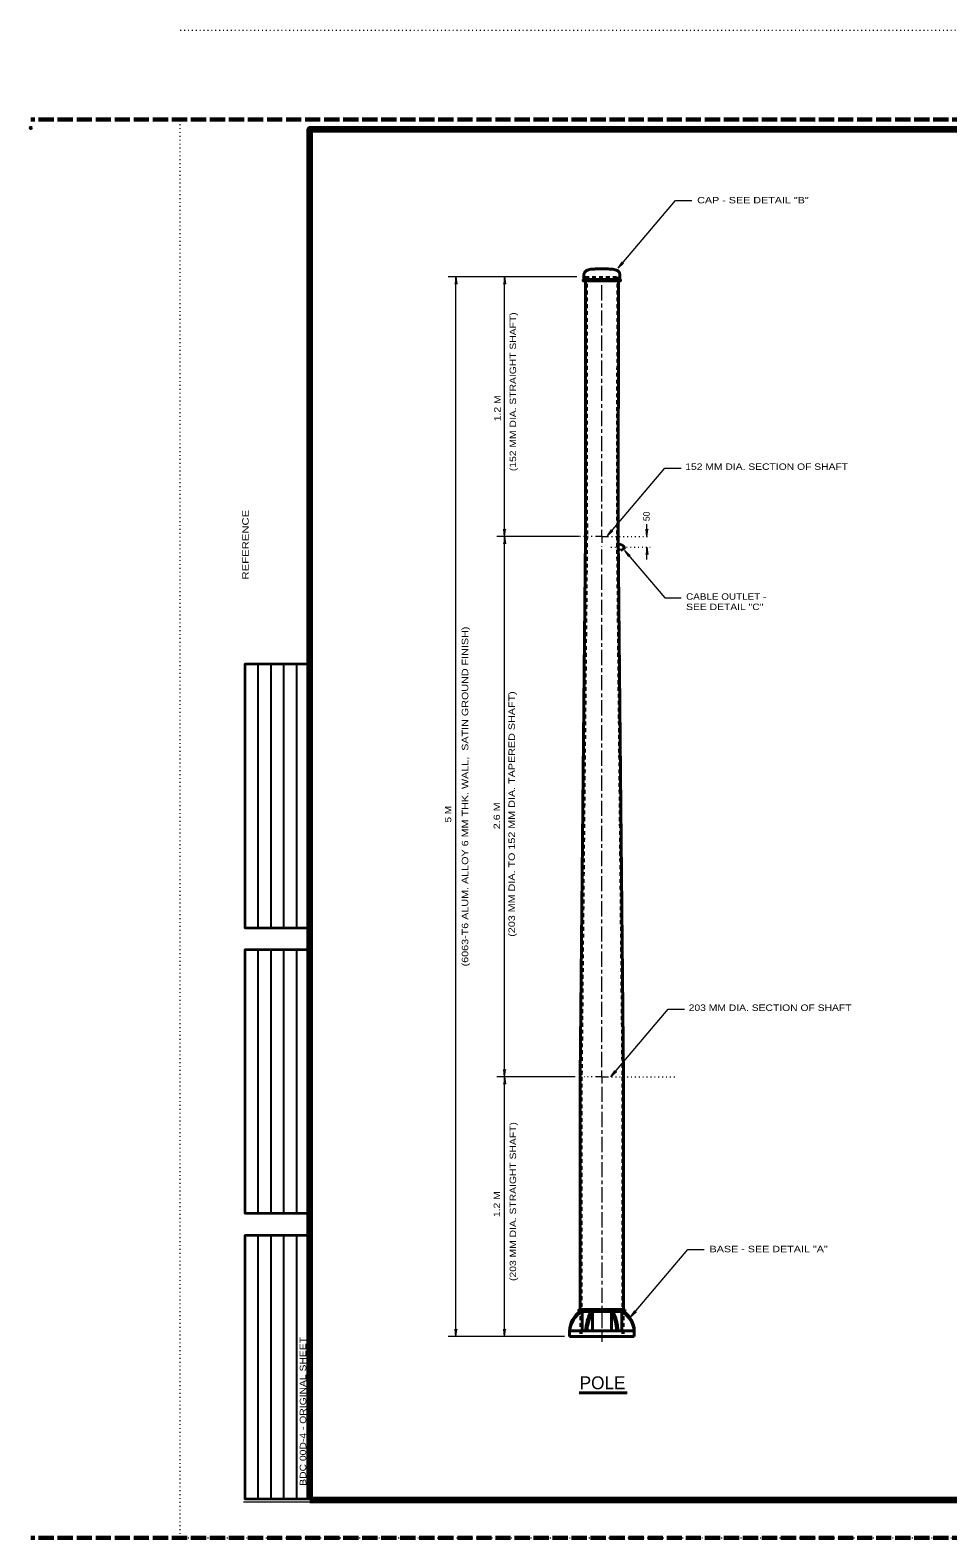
# Model space of a CAD drawing. Extents: x 312583 to 312854, y 144419 to 144597.
# Drawn here: x 312583.5 to 312691.9, y 144418.6 to 144596.8 of the extents above; entities that cross this region are included whole.
import ezdxf
from ezdxf.enums import TextEntityAlignment as Align

# ---------------------------------------------------------------- set-up
doc = ezdxf.new("R2010")
doc.units = 0
doc.header["$LTSCALE"] = 0.3
doc.header["$PDMODE"] = 32
doc.header["$PDSIZE"] = 0.15
for name, pattern in [('DOTTED', [1.5, 0.3, -1.2]), ('LONG_DASH_SHORT_DASH', [9.9, 6, -1.2, 1.5, -1.2]), ('LONG_DASHED', [7.5, 6, -1.5]), ('SHORT_DASHED', [2.7, 1.5, -1.2])]:
    doc.linetypes.add(name, pattern=pattern)
for name, color, linetype, lineweight in [('1', 7, 'Continuous', 40), ('2', 7, 'Continuous', 13), ('62', 7, 'DOTTED', 13), ('63', 7, 'LONG_DASHED', 60)]:
    doc.layers.add(name, color=color, linetype=linetype, lineweight=lineweight)

msp = doc.modelspace()

# ---------------------------------------------------------------- linework, layer by layer
at = {"layer": '1'}
for p, q in [((312653.15, 144567.2982), (312648.8413, 144567.2982)), ((312648.918, 144567.2982), (312648.918, 144567.7812)), ((312649.079, 144567.1372), (312651.034, 144567.1372)), ((312652.9967, 144567.1372), (312651.034, 144567.1372)), ((312653.15, 144567.2982), (312653.15, 144567.7812)), ((312653.15, 144567.2982), (312653.2343, 144567.2982)), ((312648.481, 144473.0595), (312648.481, 144445.5898)), ((312653.5947, 144473.0595), (312653.5947, 144445.5898)), ((312648.32, 144445.5898), (312651.034, 144445.5898)), ((312648.32, 144445.5898), (312648.32, 144445.3522)), ((312653.7557, 144445.5898), (312651.034, 144445.5898)), ((312653.7557, 144445.5898), (312653.7557, 144445.3522)), ((312648.32, 144445.3522), (312651.034, 144445.3522)), ((312648.688, 144443.0368), (312648.688, 144445.3522)), ((312649.9223, 144445.3522), (312649.9223, 144443.1135)), ((312653.7557, 144445.3522), (312651.034, 144445.3522)), ((312652.1533, 144445.3522), (312652.1533, 144443.1135)), ((312653.3877, 144443.0368), (312653.3877, 144445.3522)), ((312647.2007, 144443.0368), (312651.034, 144443.0368)), ((312647.2007, 144443.0368), (312647.2007, 144442.3928)), ((312647.2007, 144442.3928), (312651.034, 144442.3928)), ((312654.8673, 144443.0368), (312651.034, 144443.0368)), ((312654.8673, 144442.3928), (312651.034, 144442.3928)), ((312654.8673, 144443.0368), (312654.8673, 144442.3928))]:
    msp.add_line(p, q, dxfattribs=at)
at = {"layer": '1', "linetype": 'SHORT_DASHED', "lineweight": 25}
for p, q in [((312649.079, 144567.6202), (312649.079, 144567.1372)), ((312649.079, 144567.6202), (312652.9967, 144567.6202)), ((312652.9967, 144567.6202), (312652.9967, 144567.1372)), ((312652.9737, 144536.0182), (312652.8127, 144536.0182)), ((312652.9737, 144535.4125), (312652.8127, 144535.4125)), ((312648.642, 144473.0595), (312648.642, 144445.5898)), ((312653.4337, 144473.0595), (312653.4337, 144445.5898)), ((312648.481, 144445.5898), (312648.481, 144442.3928)), ((312648.642, 144445.5898), (312648.642, 144442.3928)), ((312653.4337, 144445.5898), (312653.4337, 144442.3928)), ((312653.5947, 144445.5898), (312653.5947, 144442.3928))]:
    msp.add_line(p, q, dxfattribs=at)
at = {"layer": '1', "linetype": 'DOTTED', "lineweight": 13}
msp.add_line((312652.0997, 144535.6732), (312656.7457, 144535.6732), dxfattribs=at)
at = {"layer": '1', "lineweight": 35}
msp.add_line((312653.771, 144535.6042), (312653.2573, 144535.2822), dxfattribs=at)
at = {"layer": '1', "lineweight": 25}
for p, q in [((312610.4087, 144490.6573), (312610.4087, 144521.8756)), ((312611.9315, 144490.6573), (312611.9315, 144521.8756)), ((312613.4543, 144490.6573), (312613.4543, 144521.8756)), ((312614.9772, 144490.6573), (312614.9772, 144521.8756)), ((312610.4087, 144456.901), (312610.4087, 144488.1192)), ((312611.9315, 144456.901), (312611.9315, 144488.1192)), ((312613.4543, 144456.901), (312613.4543, 144488.1192)), ((312614.9772, 144456.901), (312614.9772, 144488.1192)), ((312610.4087, 144423.1446), (312610.4087, 144454.3629)), ((312611.9315, 144423.1446), (312611.9315, 144454.3629)), ((312613.4543, 144423.1446), (312613.4543, 144454.3629)), ((312614.9772, 144423.1446), (312614.9772, 144454.3629)), ((312648.32, 144445.5898), (312648.481, 144445.7508)), ((312653.7557, 144445.5898), (312653.5947, 144445.7508))]:
    msp.add_line(p, q, dxfattribs=at)
at = {"layer": '1', "lineweight": 13}
msp.add_line((312608.6858, 144422.8446), (312616.5, 144422.8446), dxfattribs=at)
at = {"layer": '1', "lineweight": 158}
msp.add_line((312616.5, 144423.0846), (312849, 144423.0846), dxfattribs=at)
msp.add_lwpolyline([(312616.5, 144423.1446), (312616.5, 144585.0846), (312849, 144585.0846)], dxfattribs=at)
at = {"layer": '1'}
for points in [[(312649.079, 144567.1372), (312649.1173, 144536.9535), (312648.481, 144473.0595)], [(312649.079, 144567.1372), (312648.8413, 144567.1372), (312648.8413, 144567.2982)], [(312652.9967, 144567.1372), (312652.9507, 144536.9535), (312653.5947, 144473.0595)], [(312652.9967, 144567.1372), (312653.2343, 144567.1372), (312653.2343, 144567.2982)]]:
    msp.add_lwpolyline(points, dxfattribs=at)
at = {"layer": '1', "linetype": 'SHORT_DASHED', "lineweight": 25}
for points in [[(312649.24, 144567.6202), (312649.2783, 144536.9535), (312648.642, 144473.0595)], [(312652.8357, 144567.6202), (312652.7973, 144536.9535), (312653.4337, 144473.0595)]]:
    msp.add_lwpolyline(points, dxfattribs=at)
at = {"layer": '1', "lineweight": 35}
for points in [[(312616.5, 144490.6573), (312608.8858, 144490.6573), (312608.8858, 144521.8756), (312616.5, 144521.8756)], [(312616.5, 144456.901), (312608.8858, 144456.901), (312608.8858, 144488.1192), (312616.5, 144488.1192)], [(312616.5, 144423.1446), (312608.8858, 144423.1446), (312608.8858, 144454.3629), (312616.5, 144454.3629)]]:
    msp.add_lwpolyline(points, dxfattribs=at)
for radius in [0.8766, 0.2652]:
    msp.add_arc((312653.0283, 144535.1447), radius, 31.85561, 93.74313, dxfattribs=at)
at = {"layer": '1'}
for centre, radius, start, end in [((312650.1327, 144442.9268), 2.9315, 124.21849, 177.88724), ((312650.4187, 144442.6088), 3.2435, 122.28719, 172.4519), ((312655.0367, 144442.6929), 5.927, 153.35491, 176.59885), ((312655.0367, 144442.6929), 5.7673, 152.55593, 176.59975), ((312647.0364, 144442.6929), 5.7673, 3.40025, 27.44407), ((312647.0364, 144442.6929), 5.927, 3.40115, 26.64509), ((312651.6544, 144442.6088), 3.2435, 7.5481, 57.71281), ((312651.9404, 144442.9268), 2.9315, 2.11276, 55.78151), ((312649.9984, 144443.1148), 0.0799, 180, 270), ((312652.0748, 144443.1148), 0.0799, 270, 0)]:
    msp.add_arc(centre, radius, start, end, dxfattribs=at)
for points in [[(312651.034, 144568.5785), (312650.5817, 144568.5708), (312649.999, 144568.5402), (312649.723, 144568.5172), (312649.447, 144568.4558), (312649.2477, 144568.3715), (312649.079, 144568.2718), (312648.9563, 144568.0802), (312648.9333, 144567.9958), (312648.918, 144567.7812)], [(312651.034, 144568.5785), (312651.4863, 144568.5708), (312652.0767, 144568.5402), (312652.345, 144568.5172), (312652.621, 144568.4558), (312652.828, 144568.3715), (312652.989, 144568.2718), (312653.1117, 144568.0802), (312653.1423, 144567.9958), (312653.15, 144567.7812)]]:
    msp.add_spline(points, degree=3, dxfattribs=at)
msp.add_point((312583.526, 144585.2246), dxfattribs=at)
at = {"layer": '2'}
for p, q in [((312652.966, 144568.6475), (312659.7433, 144576.6515)), ((312659.7433, 144576.6515), (312661.66, 144576.6515)), ((312652.966, 144568.6475), (312653.4413, 144569.3758)), ((312652.966, 144568.6475), (312653.6023, 144569.2378)), ((312653.4413, 144569.3758), (312653.3417, 144569.0998)), ((312653.6023, 144569.2378), (312653.3417, 144569.0998)), ((312648.0823, 144567.6202), (312632.8717, 144567.6202)), ((312633.784, 144567.6202), (312633.6767, 144566.7538)), ((312633.6767, 144566.7538), (312633.784, 144567.0298)), ((312633.784, 144442.3928), (312633.784, 144567.6202)), ((312633.784, 144567.6202), (312633.8913, 144566.7538)), ((312633.8913, 144566.7538), (312633.784, 144567.0298)), ((312639.534, 144567.6202), (312639.4267, 144566.7538)), ((312639.4267, 144566.7538), (312639.534, 144567.0298)), ((312639.534, 144536.9535), (312639.534, 144567.6202)), ((312639.534, 144567.6202), (312639.6413, 144566.7538)), ((312639.6413, 144566.7538), (312639.534, 144567.0298)), ((312656.3623, 144536.9535), (312656.3623, 144538.39)), ((312648.3123, 144536.9535), (312638.6217, 144536.9535)), ((312639.4267, 144537.8198), (312639.534, 144537.5438)), ((312639.534, 144536.9535), (312639.4267, 144537.8198)), ((312639.534, 144536.9535), (312639.4267, 144536.0872)), ((312639.4267, 144536.0872), (312639.534, 144536.3632)), ((312639.6413, 144537.8198), (312639.534, 144537.5438)), ((312639.534, 144536.9535), (312639.6413, 144537.8198)), ((312639.534, 144473.0595), (312639.534, 144536.9535)), ((312639.534, 144536.9535), (312639.6413, 144536.0872)), ((312639.6413, 144536.0872), (312639.534, 144536.3632)), ((312651.034, 144536.9535), (312650.2673, 144536.9535)), ((312651.034, 144536.9535), (312651.034, 144537.7202)), ((312651.034, 144536.9535), (312651.034, 144537.7202)), ((312651.034, 144536.9535), (312651.8007, 144536.9535)), ((312651.034, 144536.9535), (312651.034, 144536.1868)), ((312651.701, 144537.0072), (312652.1763, 144537.7432)), ((312651.701, 144537.0072), (312652.3373, 144537.6052)), ((312652.1763, 144537.7432), (312652.0767, 144537.4595)), ((312652.3373, 144537.6052), (312652.0767, 144537.4595)), ((312656.255, 144537.8198), (312656.3623, 144537.5438)), ((312656.3623, 144536.9535), (312656.255, 144537.8198)), ((312656.4697, 144537.8198), (312656.3623, 144537.5438)), ((312656.3623, 144536.9535), (312656.4697, 144537.8198)), ((312653.725, 144535.2898), (312654.369, 144534.6995)), ((312653.725, 144535.2898), (312654.2003, 144534.5615)), ((312654.369, 144534.6995), (312654.1083, 144534.8375)), ((312654.2003, 144534.5615), (312654.1083, 144534.8375)), ((312656.3623, 144535.6732), (312656.255, 144534.8068)), ((312656.255, 144534.8068), (312656.3623, 144535.0828)), ((312656.3623, 144534.2055), (312656.3623, 144535.6732)), ((312656.3623, 144535.6732), (312656.4697, 144534.8068)), ((312656.4697, 144534.8068), (312656.3623, 144535.0828)), ((312652.0997, 144473.0672), (312658.8847, 144481.0635)), ((312658.8847, 144481.0635), (312660.8013, 144481.0635)), ((312639.4267, 144473.9335), (312639.534, 144473.6498)), ((312639.534, 144473.0595), (312639.4267, 144473.9335)), ((312639.6413, 144473.9335), (312639.534, 144473.6498)), ((312639.534, 144473.0595), (312639.6413, 144473.9335)), ((312647.883, 144473.0595), (312638.6217, 144473.0595)), ((312639.534, 144473.0595), (312639.4267, 144472.1932)), ((312639.4267, 144472.1932), (312639.534, 144472.4692)), ((312639.534, 144442.3928), (312639.534, 144473.0595)), ((312639.534, 144473.0595), (312639.6413, 144472.1932)), ((312639.6413, 144472.1932), (312639.534, 144472.4692)), ((312651.034, 144473.0595), (312650.2673, 144473.0595)), ((312651.034, 144473.0595), (312651.034, 144473.8262)), ((312651.034, 144473.0595), (312651.034, 144473.8262)), ((312651.034, 144473.0595), (312651.8007, 144473.0595)), ((312651.034, 144473.0595), (312651.034, 144472.2928)), ((312652.0997, 144473.0672), (312652.5827, 144473.7955)), ((312652.0997, 144473.0672), (312652.7437, 144473.6575)), ((312652.5827, 144473.7955), (312652.483, 144473.5118)), ((312652.7437, 144473.6575), (312652.483, 144473.5118)), ((312654.4303, 144444.6775), (312661.2077, 144452.6815)), ((312661.2077, 144452.6815), (312663.1243, 144452.6815)), ((312654.4303, 144444.6775), (312654.9133, 144445.4058)), ((312654.9133, 144445.4058), (312654.8137, 144445.1298)), ((312654.4303, 144444.6775), (312655.0743, 144445.2678)), ((312655.0743, 144445.2678), (312654.8137, 144445.1298)), ((312646.6257, 144442.3928), (312632.8717, 144442.3928)), ((312633.6767, 144443.2668), (312633.784, 144442.9832)), ((312633.784, 144442.3928), (312633.6767, 144443.2668)), ((312633.8913, 144443.2668), (312633.784, 144442.9832)), ((312633.784, 144442.3928), (312633.8913, 144443.2668)), ((312639.4267, 144443.2668), (312639.534, 144442.9832)), ((312639.534, 144442.3928), (312639.4267, 144443.2668)), ((312639.6413, 144443.2668), (312639.534, 144442.9832)), ((312639.534, 144442.3928), (312639.6413, 144443.2668))]:
    msp.add_line(p, q, dxfattribs=at)
at = {"layer": '2', "linetype": 'LONG_DASH_SHORT_DASH'}
for p, q in [((312651.034, 144538.1035), (312651.034, 144567.6202)), ((312651.034, 144474.2095), (312651.034, 144535.8035)), ((312651.034, 144471.9095), (312651.034, 144441.7488))]:
    msp.add_line(p, q, dxfattribs=at)
at = {"layer": '2', "linetype": 'DOTTED'}
for p, q in [((312649.884, 144536.9535), (312642.2173, 144536.9535)), ((312652.184, 144536.9535), (312656.7457, 144536.9535)), ((312649.884, 144473.0595), (312648.941, 144473.0595)), ((312652.184, 144473.0595), (312659.8507, 144473.0595))]:
    msp.add_line(p, q, dxfattribs=at)
at = {"layer": '2', "lineweight": 40}
msp.add_line((312648.3325, 144435.7354), (312654.0076, 144435.7354), dxfattribs=at)
at = {"layer": '2'}
for points in [[(312651.701, 144537.0072), (312658.4783, 144545.0112), (312660.395, 144545.0112)], [(312653.725, 144535.2898), (312658.4783, 144529.6778), (312660.395, 144529.6778)]]:
    msp.add_lwpolyline(points, dxfattribs=at)
at = {"layer": '62'}
for p, q in [((312601.2, 144596.7846), (312853.5, 144596.7846)), ((312601.2, 144418.5846), (312601.2, 144586.2246))]:
    msp.add_line(p, q, dxfattribs=at)
msp.add_lwpolyline([(312601.2, 144418.5846), (312853.5, 144418.5846), (312853.5, 144596.7846)], dxfattribs=at)
at = {"layer": '63'}
for p, q in [((312851.75, 144586.2246), (312583.526, 144586.2246)), ((312851.75, 144418.5846), (312583.526, 144418.5846))]:
    msp.add_line(p, q, dxfattribs=at)

# ---------------------------------------------------------------- texts
at = {"layer": '1'}
for s, height, width, p in [('REFERENCE                                                              ', 0.7682, 1.3, (312609.2854, 144531.8549)), ('BDC 00D-4 - ORIGINAL SHEET', 0.7614, 1.2, (312616.0832, 144424.7374))]:
    msp.add_text(s, height=height, rotation=90, dxfattribs=dict(at, width=width)).set_placement(p)
at = {"layer": '2'}
for s, width, p in [('CAP - SEE DETAIL "B"', 1.25, (312662.2963, 144576.3124)), ('152 MM DIA. SECTION OF SHAFT', 1.2, (312660.8911, 144544.8125)), ('CABLE OUTLET -', 1.15, (312660.993, 144529.4622)), ('SEE DETAIL "C"', 1.2, (312660.993, 144528.2422)), ('203 MM DIA. SECTION OF SHAFT', 1.2, (312661.2976, 144480.8648)), ('BASE - SEE DETAIL "A"', 1.25, (312663.7683, 144452.3425))]:
    msp.add_text(s, height=0.76, dxfattribs=dict(at, width=width)).set_placement(p)
for s, width, p in [('(152 MM DIA. STRAIGHT SHAFT)', 1.2, (312640.8941, 144544.6635)), ('1.2 M', 1.2, (312639.0633, 144550.5655)), ('(6063-T6 ALUM. ALLOY 6 MM THK. WALL,  SATIN GROUND FINISH)', 1.25, (312635.2361, 144486.1247)), ('(203 MM DIA. TO 152 MM DIA. TAPERED SHAFT)', 1.25, (312640.754, 144489.6259)), ('5 M', 1.15, (312633.2432, 144503.136)), ('2.6 M', 1.25, (312638.9933, 144502.337)), ('(203 MM DIA. STRAIGHT SHAFT)', 1.2, (312640.8958, 144448.9459)), ('1.2 M', 1.2, (312638.9933, 144456.496))]:
    msp.add_text(s, height=0.76, rotation=90, dxfattribs=dict(at, width=width)).set_placement(p)
msp.add_text('50', height=0.76, rotation=90, dxfattribs=at).set_placement((312656.6808, 144538.7543))
msp.add_text('POLE', height=1.52, dxfattribs=at).set_placement((312651.119, 144436.1506), align=Align.CENTER)

doc.saveas('drawing.dxf')
